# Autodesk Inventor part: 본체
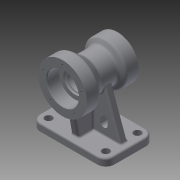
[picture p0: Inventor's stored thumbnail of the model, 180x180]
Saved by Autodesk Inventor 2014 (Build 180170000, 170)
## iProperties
Created: 2015-08
Part Number: 본체
Material: 일반
Document SubType Name: Modeling
Designer: SEC
Density: 1 g/cm^3
Appearance: 기본값
Author: SEC
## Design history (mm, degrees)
sketch "스케치1"
  geometry: L1 (47, -40)-(-47, -40); L2 (-61, -26)-(-61, 26); L3 (-47, 40)-(47, 40); L4 (61, 26)-(61, -26); C1 r 6 at (47, -26); C2 r 6 at (-47, -26); C3 r 6 at (-47, 26); C4 r 6 at (47, 26); A1 r 14 centre (47, -26) between (47, -40) and (61, -26); A2 r 14 centre (-47, -26) between (-61, -26) and (-47, -40); A3 r 14 centre (-47, 26) between (-47, 40) and (-61, 26); A4 r 14 centre (47, 26) between (61, 26) and (47, 40); 6 further points
  constraints: 8 centre point, 8 end point, 8 point on circle, 8 tangent, 6 point on line, 4 coincident, 3 equal radius, 2 midpoint, 2 parallel, 1 horizontal, 1 horizontal alignment, 1 perpendicular, 1 vertical alignment
  dimensions: "d0" = 122 distance of point (-61, 40) point (61, 40); "d1" = 80 distance of point (-61, -40) point (-61, 40); "d2" = 14 radius of A1; "d3" = 12 diameter of C1; "d4" = 12 diameter of C2; "d5" = 12 diameter of C3; "d6" = 12 diameter of C4
extrude "돌출1" new body sketch "스케치1" distance "d7" = 12; taper "d8" = 0 deg
fillet "모깎기1" dims "d9" = 3
node "작업 평면1"
sketch "스케치8"
  geometry: L1 (-11, 12)-(63, 12) reference; L2 (66, 9)-(66, 0) reference; L3 (66, 0)-(-14, 0) reference; L4 (-14, 0)-(-14, 9) reference; L5 (56, 12)-(56, 63); L6 (-3.916, 12)-(-11.361, 54.226); L7 (56, 63)-(43.836, 69); L8 (43.836, 69)-(10.98, 67.65); L9 (10.98, 67.65)-(-11.361, 54.226); L10 (56, 12)-(56.285, 5.07); L11 (56.285, 5.07)-(-2.593, 4.5); L12 (-2.593, 4.5)-(-3.916, 12); A1 r 3 centre (-11, 9) between (-11, 12) and (-14, 9) reference; A2 r 3 centre (63, 9) between (66, 9) and (63, 12) reference; 1 further point
  constraints: 16 end point, 2 perpendicular, 2 point on line, 1 collinear
extrude "돌출2" join sketch "스케치8" stored distance "d92" = 12; taper "d93" = 0 deg
node "작업 평면2"
sketch "스케치9"
  geometry: L1 (-11, 12)-(41, 12) reference; L2 (41, 12)-(41, 68.267) reference; L3 (53, 68.267)-(53, 12) reference; L4 (53, 12)-(105, 12) reference; L5 (108, 9)-(108, 0) reference; L6 (108, 0)-(-14, 0) reference; L7 (-14, 0)-(-14, 9) reference; L8 (98, 12)-(71.141, 85.795); L9 (-4.245, 11.383)-(22.354, 85.272); L10 (-4.245, 11.383)-(-6.059, 6.342); L11 (-6.059, 6.342)-(100.73, 4.5); L12 (100.73, 4.5)-(98, 12); L13 (22.354, 85.272)-(38.51, 70.192); L14 (38.51, 70.192)-(56.29, 69.885); L15 (56.29, 69.885)-(71.141, 85.795); L16 (41, 68.267)-(53, 68.267) reference; A1 r 3 centre (-11, 9) between (-11, 12) and (-14, 9) reference; A2 r 3 centre (105, 9) between (108, 9) and (105, 12) reference; 1 further point
  constraints: 16 end point, 2 collinear, 1 parallel, 1 perpendicular, 1 point on line
extrude "돌출3" join sketch "스케치9" stored distance "d96" = 12; taper "d97" = 0 deg
fillet "모깎기5" dims "d98" = 3
fillet "모깎기6" dims "d99" = 3
node "작업 평면3"
sketch "스케치10"
  geometry: L1 (43.836, 69)-(56, 63) reference; L2 (56, 63)-(56, 15) reference; L3 (59, 12)-(63, 12) reference; L4 (66, 9)-(66, 0) reference; L5 (66, 0)-(-14, 0) reference; L6 (-14, 0)-(-14, 9) reference; L7 (-11, 12)-(-7.491, 12) reference; L8 (-4.536, 15.521)-(-11.361, 54.226) reference; L9 (-11.361, 54.226)-(10.98, 67.65) reference; L10 (10.98, 67.65)-(20, 68.021) reference; L11 (20, 68.021)-(20, 70.045) reference; L12 (20, 70.045)-(32, 70.045) reference; L13 (32, 70.045)-(32, 68.514) reference; L14 (32, 68.514)-(43.836, 69) reference; L15 (66, 0)-(66, 90); L16 (66, 90)-(-24, 90); L17 (66, 90)-(66, 125); L18 (66, 125)-(46, 125); L19 (46, 125)-(40.804, 116); L20 (40.804, 116)-(12.685, 116); L21 (12.685, 116)-(-4, 130); L22 (-4, 130)-(-24, 130); L23 (-24, 130)-(-24, 90); A1 r 3 centre (59, 15) between (56, 15) and (59, 12) reference; A2 r 3 centre (63, 9) between (66, 9) and (63, 12) reference; A3 r 3 centre (-11, 9) between (-11, 12) and (-14, 9) reference; A4 r 3 centre (-7.491, 15) between (-7.491, 12) and (-4.536, 15.521) reference; 1 further point
  constraints: 18 end point, 4 parallel, 3 perpendicular
  dimensions: "d101" = 90 distance of L4.end L15.end; "d102" = 90 distance of L15.end L16.end; "d103" = 80 diameter of L22 L16; "d104" = 70 diameter of L18 L16; "d105" = 60 deg angle of L19 L20; "d106" = 40 deg angle of L21 L16; "d107" = 20 distance of L17.end L18.end; "d108" = 20 distance of L21.end L22.end; "d109" = 52 diameter of L20 L16
revolve "회전2" sketch "스케치10" stored, may be unused: angle "d110" = 90 deg
fillet "모깎기8" dims "d111" = 5
fillet "모깎기9" dims "d112" = 3
sketch "스케치11" dims "d113" = 66
  geometry: C1 r 40 at (0, 0) reference; 3 further points
  constraints: 1 coincident, 1 vertical alignment, 2 other
hole "구멍5" sketch "스케치11" at (0, 33) diameter "d114" = 3.242; stored, may be unused: countersink angle "d118" = 82 deg, drill point angle "d120" = 118 deg; dims "d115" = 10, "d116" = 3.023, "d117" = 17, "d119" = 13
sketch "스케치12" dims "d124" = 54
  geometry: C1 r 35 at (0, 0) reference; 3 further points
  constraints: 1 coincident, 1 vertical alignment, 2 other
hole "구멍6" sketch "스케치12" at (0, 27) diameter "d125" = 3.242; stored, may be unused: countersink angle "d129" = 82 deg, drill point angle "d131" = 118 deg; dims "d126" = 10, "d127" = 3.023, "d128" = 17, "d130" = 13
sketch "스케치13"
  geometry: C1 r 40 at (0, 0) reference; 1 further point
hole "구멍7" sketch "스케치13" at (0, 0) diameter "d135" = 38; stored, may be unused: countersink angle "d139" = 82 deg, drill point angle "d141" = 0 deg; dims "d136" = 10, "d137" = 52, "d138" = 20, "d140" = 23
sketch "스케치14"
  geometry: C1 r 35 at (0, 0) reference; 1 further point
hole "구멍8" sketch "스케치14" at (0, 0) diameter "d142" = 32; stored, may be unused: countersink angle "d146" = 82 deg, drill point angle "d148" = 0 deg; dims "d143" = 10, "d144" = 40, "d145" = 17, "d147" = 90
chamfer "모따기2" distance "d149" = 1; stored, may be unused: second distance "d150" = 2, angle "d151" = 45 deg
fillet "모깎기10" dims "d152" = 0.3
fillet "모깎기11" dims "d153" = 3
sketch "스케치16"
  geometry: L1 (38, 62.432)-(38, 15) reference; L2 (47, 0)-(23, 0); L3 (23, 0)-(23, 30); L4 (29, 30)-(29.002, 35.998); L5 (17.002, 36.002)-(17, 30.002); A1 r 6 centre (23, 30) between (23.002, 36) and (29, 30); A2 r 6 centre (23.002, 36) between (29.002, 35.998) and (17.002, 36.002)
  constraints: 8 end point, 5 point on circle, 3 tangent, 2 centre point, 2 perpendicular, 1 coincident
  dimensions: "d163" = 24 distance of L2.start L2.end; "d164" = 30 distance of L2.end L3.end; "d165" = 12 diameter of A1; "d166" = 12 diameter of A2
extrude "돌출5" cut sketch "스케치16" stored distance "d167" = 12; taper "d168" = 0 deg
sketch "스케치17"
  geometry: L1 (5.82, 47.952)-(7.209, 47.952) reference; L2 (-17, 62.432)-(-14.504, 62.432) reference; L3 (-17, 15)-(-17, 62.432) reference; L4 (-17, 15)-(1.398, 15) reference; L5 (1.398, 15)-(7.209, 47.952) reference; L6 (24, 50.453)-(12.111, 50.453) reference; L7 (24, 63.675)-(24, 50.453) reference; L8 (4.3, 64.702)-(23, 64.702) reference; L9 (4, 71.972)-(4, 65.01) reference; L10 (-49, 75.168)-(1, 75.168) reference; L11 (-49, 71.236)-(-49, 75.168) reference; L12 (-65, 70.921)-(-49.3, 70.921) reference; L13 (-66, 55.518)-(-66, 69.875) reference; L14 (-57.863, 55.518)-(-66, 55.518) reference; L15 (-53, 53.081)-(-48.887, 53.081) reference; L16 (-37.917, 62.432)-(-35, 62.432) reference; L17 (-35, 62.432)-(-35, 15) reference; L18 (-53, 15)-(-35, 15) reference; L19 (-53, 53.081)-(-53, 15) reference; L20 (6.675, 12)-(11, 12) reference; L21 (14, 9)-(14, 0) reference; L22 (14, 0)-(-66, 0) reference; L23 (-66, 0)-(-66, 9) reference; L24 (-63, 12)-(-58.196, 12) reference; L25 (5.82, 129.547)-(24, 129.547) reference; L26 (24, 129.547)-(24, 116.325) reference; L27 (23, 115.298)-(4.3, 115.298) reference; L28 (4, 114.99)-(4, 108.028) reference; L29 (1, 104.832)-(-49, 104.832) reference; L30 (-49, 104.832)-(-49, 108.764) reference; L31 (-49.3, 109.079)-(-65, 109.079) reference; L32 (-66, 110.125)-(-66, 124.482) reference; L33 (-66, 124.482)-(-48.887, 124.482) reference; L34 (-37.917, 115.298)-(-14.504, 115.298) reference; L35 (-66, 0)-(-40, 0); L36 (-40, 0)-(-40, 36); A1 r 3 centre (11, 9) between (14, 9) and (11, 12) reference; A2 r 3 centre (-63, 9) between (-63, 12) and (-66, 9) reference; 10 further points
  constraints: 4 end point, 1 coincident, 1 perpendicular, 1 point on line, 27 other
  dimensions: "d169" = 26 distance of L22.end L35.end; "d170" = 36 distance of L35.end L36.end
feature "엠보싱1" sketch "스케치17" dims "d0" = 122, "d1" = 80, "d2" = 14, "d3" = 12, "d4" = 12, "d5" = 12, "d6" = 12, "d171" = 0.5, "d172" = 0
node "솔리드1"
pattern_circular "원형 패턴3" dims angle "d122" = 360 deg
pattern_circular "원형 패턴4" dims angle "d133" = 360 deg
mirror "대칭1"
node "절단 모서리 투영3"
node "절단 모서리 투영4"
node "절단 모서리 투영5"
node "절단 모서리 투영6"
